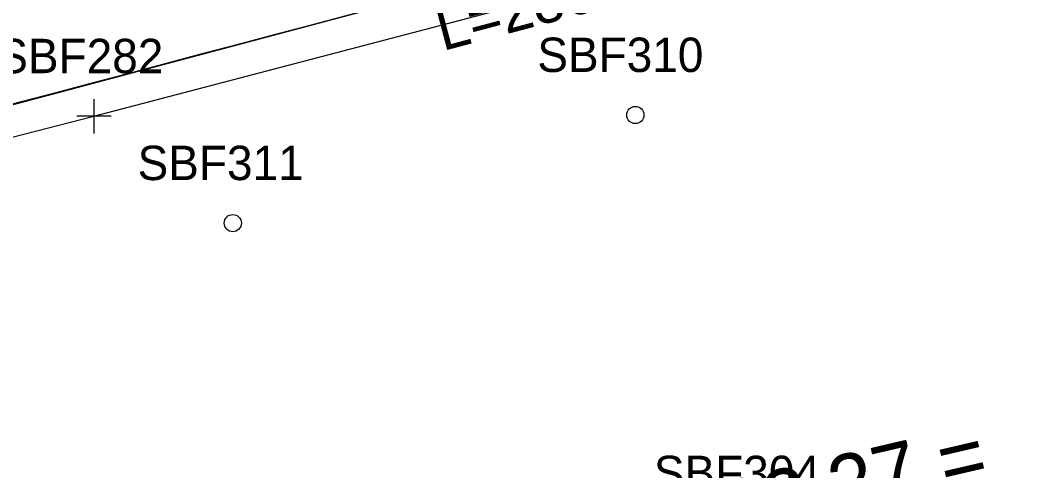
# Model space of a CAD drawing. Extents: x 818717 to 846077, y 440014 to 541392.
# Drawn here: x 831497.6 to 831616.5, y 492976.5 to 493028.8 of the extents above; entities that cross this region are included whole.
import ezdxf

# ---------------------------------------------------------------- set-up
doc = ezdxf.new("R2010")
doc.units = 0
for name, color, linetype in [('SURVEY - CENTERLINE - Preliminary Text', 7, 'Continuous'), ('SURVEY - DTM - Breaklines', 7, 'Continuous'), ('SURVEY - DTM - Breaklines - Points - Locators', 7, 'Continuous'), ('SURVEY - DTM - Breaklines - Points - Numbers', 7, 'Continuous'), ('SURVEY - DTM - Spot Points - Locators', 7, 'Continuous'), ('SURVEY - DTM - Spot Points - Point Numbers', 7, 'Continuous'), ('SURVEY - PROPERTY - ROW Lines', 7, 'Continuous'), ('SURVEY - PROPERTY - ROW Lines Text', 7, 'Continuous'), ('SURVEY - UTILITIES - Electric (Overhead) with Text', 7, 'Continuous')]:
    doc.layers.add(name, color=color, linetype=linetype)

msp = doc.modelspace()

# ---------------------------------------------------------------- linework, layer by layer
at = {"layer": 'SURVEY - DTM - Breaklines'}
msp.add_lwpolyline([(831362.8, 492979.81), (831376.24, 492982.73), (831405.77, 492991.28), (831454.7, 493004.49), (831506.17, 493017.71), (831556.95, 493031), (831608.27, 493041.82), (831657.28, 493058.44), (831693.45, 493071.62), (831709.12, 493073.94), (831712.7, 493059.63), (831718.93, 493040.56), (831729.91, 492991.41)], dxfattribs=at)
at = {"layer": 'SURVEY - DTM - Breaklines - Points - Locators'}
for p, q in [((831506.17, 493019.71), (831506.17, 493015.71)), ((831508.17, 493017.71), (831504.17, 493017.71))]:
    msp.add_line(p, q, dxfattribs=at)
at = {"layer": 'SURVEY - DTM - Spot Points - Locators'}
for centre in [(831569.19, 493017.85), (831522.34, 493005.28)]:
    msp.add_circle(centre, 1, dxfattribs=at)
at = {"layer": 'SURVEY - PROPERTY - ROW Lines'}
msp.add_arc((818719.06, 541389.92), 50030, 284.715401, 285.043654, dxfattribs=at)
at = {"layer": 'SURVEY - UTILITIES - Electric (Overhead) with Text'}
msp.add_lwpolyline([(832667.18, 493331.74), (832415.28, 493266.23), (832147.85, 493195.27), (831907.96, 493131.64), (831666.03, 493064.14), (831375.19, 492986.65), (831101.3, 492913.04)], dxfattribs=at)

# ---------------------------------------------------------------- texts
at = {"layer": 'SURVEY - CENTERLINE - Preliminary Text'}
msp.add_text('SR87 STA. 108+22.27 =', height=7, rotation=13.0771, dxfattribs=at).set_placement((831511.26, 492952.12))
at = {"layer": 'SURVEY - DTM - Breaklines - Points - Numbers'}
msp.add_text('SBF282', height=4, dxfattribs=at).set_placement((831494.93, 493022.71))
at = {"layer": 'SURVEY - DTM - Spot Points - Point Numbers'}
for s, p in [('SBF310', (831557.78, 493022.85)), ('SBF311', (831511.26, 493010.28)), ('SBF304', (831571.34, 492974.23))]:
    msp.add_text(s, height=4, dxfattribs=at).set_placement(p)
at = {"layer": 'SURVEY - PROPERTY - ROW Lines Text'}
msp.add_text("L=286.63'", height=5, rotation=14.8795, dxfattribs=at).set_placement((831546.76, 493025.27))

doc.saveas('drawing.dxf')
